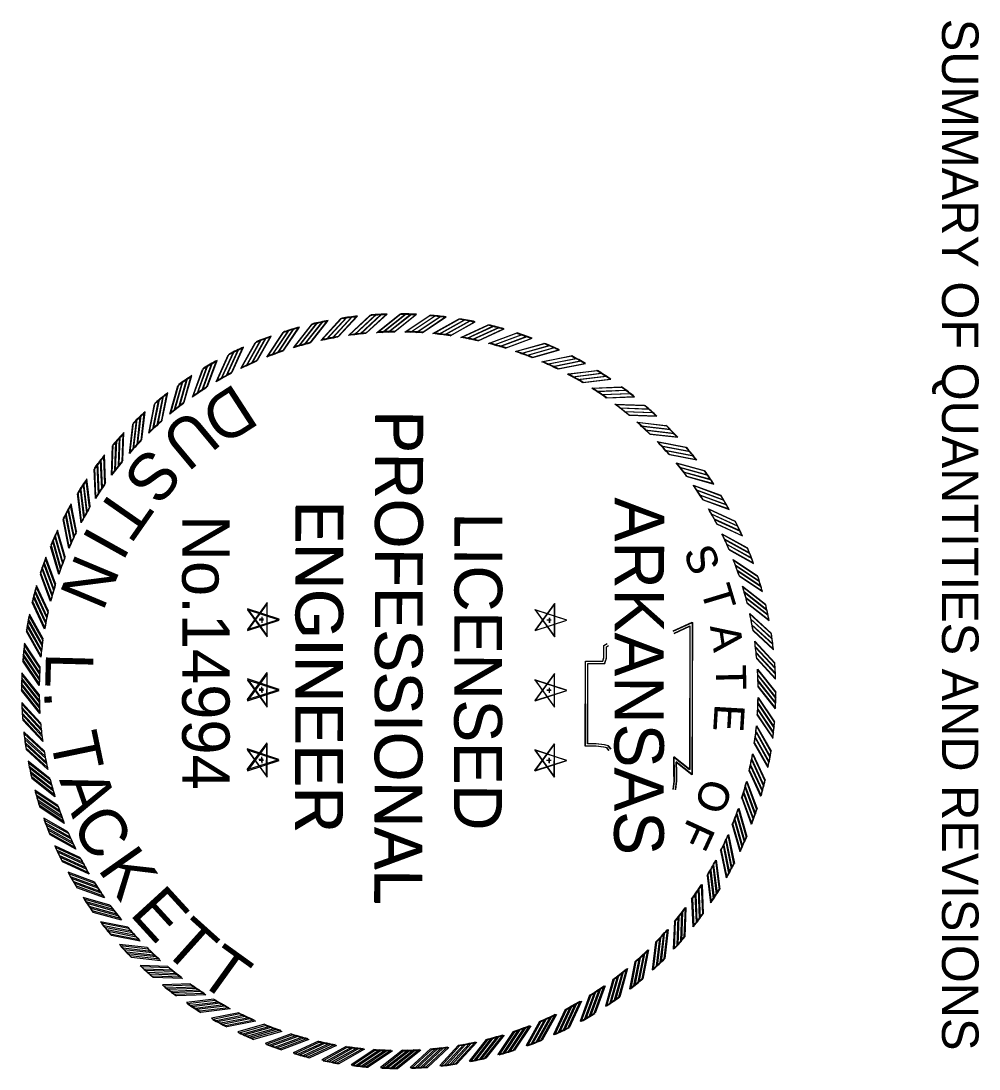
# Model space of a CAD drawing. Extents: x -206535075 to -206533174, y 123969740 to 123973355.
# Drawn here: x -206533482.2 to -206533174.1, y 123970261.6 to 123970598.7 of the extents above; entities that cross this region are included whole.
import ezdxf

# ---------------------------------------------------------------- set-up
doc = ezdxf.new("R2010")
doc.units = 0
doc.layers.add('54', color=7, linetype='Continuous')
doc.layers.add('Default', color=7, linetype='Continuous')

# ---------------------------------------------------------------- blocks, each defined once
blk = doc.blocks.new('STAR')
at = {"layer": 'Default'}
for p, q in [((-0.0001, 0.0615), (-0.0366, -0.0504)), ((0.0362, -0.0503), (0, 0.0617)), ((0.0587, 0.0188), (-0.059, 0.0189)), ((-0.0589, 0.0188), (0.0363, -0.0505)), ((-0.0365, -0.0503), (0.0589, 0.0188)), ((-0.0085, 0), (0.009, 0)), ((0, 0.0063), (0, -0.0085))]:
    blk.add_line(p, q, dxfattribs=at)
blk = doc.blocks.new('RP')
at = {"layer": 'Default'}
for p, q in [((-0.0781, 1.2656), (0.003, 1.33)), ((-0.058, 1.2667), (0.0216, 1.3299)), ((-0.0375, 1.2674), (0.0405, 1.3294)), ((-0.0176, 1.2679), (0.059, 1.3287))]:
    blk.add_line(p, q, dxfattribs=at)
for radius, start, end in [(1.33, 87.4562, 89.8699), (1.268, 90.7933, 93.5307)]:
    blk.add_arc((0, 0), radius, start, end, dxfattribs=at)

msp = doc.modelspace()

# ---------------------------------------------------------------- linework, layer by layer
at = {"layer": 'Default'}
for points in [[(-206533272.5, 123970402.48), (-206533266.36, 123970405.32), (-206533266.33, 123970356.28), (-206533271.48, 123970360.38), (-206533271.44, 123970357.04), (-206533271.4, 123970354.26), (-206533271.7, 123970351.48)], [(-206533272.47, 123970402.39), (-206533266.32, 123970405.2), (-206533266.46, 123970356.16), (-206533271.59, 123970360.28), (-206533271.56, 123970356.94), (-206533271.53, 123970354.16), (-206533271.85, 123970351.38)], [(-206533272.14, 123970401.68), (-206533267.1, 123970403.99), (-206533267.23, 123970357.77), (-206533272.38, 123970361.91), (-206533272.34, 123970356.94), (-206533272.31, 123970354.2), (-206533272.62, 123970351.47)], [(-206533272.17, 123970401.78), (-206533267.14, 123970404.11), (-206533267.11, 123970357.89), (-206533272.28, 123970362), (-206533272.21, 123970357.03), (-206533272.18, 123970354.3), (-206533272.48, 123970351.56)], [(-206533293.15, 123970363.98), (-206533293.83, 123970364.82), (-206533294.84, 123970365.1), (-206533297.38, 123970365.39), (-206533300.77, 123970365.4), (-206533300.68, 123970392.77), (-206533296.1, 123970392.76), (-206533295.09, 123970392.75), (-206533294.74, 123970393.86), (-206533294.73, 123970397.76), (-206533293.67, 123970398.45)], [(-206533293.05, 123970364.01), (-206533293.73, 123970364.84), (-206533294.75, 123970365.12), (-206533297.29, 123970365.4), (-206533300.68, 123970365.4), (-206533300.68, 123970392.77), (-206533296.1, 123970392.77), (-206533295.09, 123970392.77), (-206533294.75, 123970393.88), (-206533294.75, 123970397.78), (-206533293.69, 123970398.47)], [(-206533292.55, 123970364.47), (-206533293.38, 123970365.5), (-206533294.7, 123970365.86), (-206533297.34, 123970366.16), (-206533299.99, 123970366.17), (-206533299.91, 123970391.99), (-206533296.11, 123970391.98), (-206533294.52, 123970391.98), (-206533293.97, 123970393.74), (-206533293.96, 123970397.34), (-206533293.25, 123970397.79)], [(-206533292.45, 123970364.5), (-206533293.29, 123970365.53), (-206533294.6, 123970365.89), (-206533297.25, 123970366.17), (-206533299.9, 123970366.17), (-206533299.9, 123970392), (-206533296.1, 123970392), (-206533294.51, 123970392), (-206533293.97, 123970393.77), (-206533293.97, 123970397.36), (-206533293.27, 123970397.82)]]:
    msp.add_lwpolyline(points, dxfattribs=at)

# ---------------------------------------------------------------- block references
for name, p, xscale, yscale, rotation in [('RP', (-206533360.74, 123970383.01), 91.17655343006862, 91.17655343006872, 13.50000010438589), ('RP', (-206533360.78, 123970383.21), 91.1765534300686, 91.17655343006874, 13.304199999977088), ('RP', (-206533360.74, 123970383.01), 91.1765534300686, 91.1765534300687, 9.00000010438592), ('RP', (-206533360.78, 123970383.21), 91.17655343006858, 91.17655343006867, 8.80419999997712), ('RP', (-206533360.74, 123970383.01), 91.17655343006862, 91.17655343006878, 4.500000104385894), ('RP', (-206533360.78, 123970383.21), 91.17655343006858, 91.17655343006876, 4.304199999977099), ('RP', (-206533360.74, 123970383.01), 91.17655343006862, 91.17655343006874, 1.0438590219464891e-07), ('RP', (-206533360.78, 123970383.21), 91.1765534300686, 91.17655343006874, -0.19580000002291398), ('RP', (-206533360.74, 123970383.01), 91.1765534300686, 91.17655343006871, -4.499999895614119), ('RP', (-206533360.78, 123970383.21), 91.17655343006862, 91.17655343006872, -4.695800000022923), ('RP', (-206533360.74, 123970383.01), 91.17655343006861, 91.17655343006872, -8.999999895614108), ('RP', (-206533360.78, 123970383.21), 91.17655343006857, 91.17655343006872, -9.195800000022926), ('RP', (-206533360.74, 123970383.01), 91.17655343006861, 91.17655343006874, -13.49999989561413), ('RP', (-206533360.78, 123970383.21), 91.1765534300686, 91.17655343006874, -13.69580000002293), ('RP', (-206533360.74, 123970383.01), 91.17655343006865, 91.17655343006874, 18.000000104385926), ('RP', (-206533360.78, 123970383.21), 91.1765534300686, 91.17655343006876, 17.804199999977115), ('RP', (-206533360.74, 123970383.01), 91.17655343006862, 91.17655343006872, -17.99999989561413), ('RP', (-206533360.78, 123970383.21), 91.17655343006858, 91.17655343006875, -18.195800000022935), ('RP', (-206533360.74, 123970383.01), 91.17655343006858, 91.17655343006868, 22.500000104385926), ('RP', (-206533360.78, 123970383.21), 91.17655343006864, 91.17655343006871, 22.30419999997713), ('RP', (-206533360.74, 123970383.01), 91.17655343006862, 91.17655343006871, -22.49999989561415), ('RP', (-206533360.78, 123970383.21), 91.1765534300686, 91.1765534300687, -22.69580000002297), ('RP', (-206533360.74, 123970383.01), 91.17655343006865, 91.17655343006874, 27.000000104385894), ('RP', (-206533360.78, 123970383.21), 91.17655343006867, 91.17655343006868, 26.804199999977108), ('RP', (-206533360.74, 123970383.01), 91.17655343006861, 91.1765534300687, -26.999999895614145), ('RP', (-206533360.78, 123970383.21), 91.17655343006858, 91.17655343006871, -27.195800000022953), ('RP', (-206533360.74, 123970383.01), 91.17655343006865, 91.17655343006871, 31.500000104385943), ('RP', (-206533360.78, 123970383.21), 91.17655343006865, 91.17655343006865, 31.304199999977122), ('RP', (-206533360.74, 123970383.01), 91.1765534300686, 91.1765534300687, -31.49999989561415), ('RP', (-206533360.78, 123970383.21), 91.17655343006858, 91.17655343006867, -31.69580000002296), ('RP', (-206533360.74, 123970383.01), 91.17655343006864, 91.1765534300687, -35.99999989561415), ('RP', (-206533360.78, 123970383.21), 91.17655343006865, 91.17655343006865, -36.19580000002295), ('RP', (-206533360.74, 123970383.01), 91.17655343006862, 91.17655343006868, 36.00000010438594), ('RP', (-206533360.78, 123970383.21), 91.17655343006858, 91.17655343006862, 35.80419999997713), ('RP', (-206533360.74, 123970383.01), 91.17655343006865, 91.17655343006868, 40.500000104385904), ('RP', (-206533360.78, 123970383.21), 91.17655343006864, 91.17655343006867, 40.30419999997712), ('RP', (-206533360.74, 123970383.01), 91.17655343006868, 91.17655343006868, -40.49999989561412), ('RP', (-206533360.78, 123970383.21), 91.17655343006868, 91.17655343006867, -40.695800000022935), ('RP', (-206533360.74, 123970383.01), 91.17655343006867, 91.17655343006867, 45.00000010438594), ('RP', (-206533360.78, 123970383.21), 91.17655343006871, 91.17655343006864, 44.80419999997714), ('RP', (-206533360.74, 123970383.01), 91.17655343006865, 91.17655343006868, -44.999999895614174), ('RP', (-206533360.78, 123970383.21), 91.17655343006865, 91.1765534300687, -45.19580000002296), ('RP', (-206533360.74, 123970383.01), 91.17655343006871, 91.1765534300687, 49.50000010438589), ('RP', (-206533360.78, 123970383.21), 91.17655343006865, 91.17655343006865, 49.304199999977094), ('RP', (-206533360.74, 123970383.01), 91.17655343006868, 91.17655343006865, -49.499999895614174), ('RP', (-206533360.78, 123970383.21), 91.17655343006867, 91.17655343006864, -49.69580000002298), ('RP', (-206533360.74, 123970383.01), 91.17655343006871, 91.17655343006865, 54.00000010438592), ('RP', (-206533360.78, 123970383.21), 91.17655343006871, 91.17655343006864, 53.80419999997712), ('RP', (-206533360.74, 123970383.01), 91.17655343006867, 91.17655343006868, -53.999999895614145), ('RP', (-206533360.78, 123970383.21), 91.17655343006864, 91.17655343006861, -54.195800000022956), ('RP', (-206533360.78, 123970383.21), 91.17655343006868, 91.17655343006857, 58.304199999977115), ('RP', (-206533360.74, 123970383.01), 91.17655343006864, 91.17655343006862, -58.49999989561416), ('RP', (-206533360.78, 123970383.21), 91.17655343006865, 91.1765534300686, -58.695800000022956), ('RP', (-206533360.74, 123970383.01), 91.1765534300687, 91.1765534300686, 58.50000010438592), ('RP', (-206533360.74, 123970383.01), 91.17655343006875, 91.17655343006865, 63.00000010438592), ('RP', (-206533360.78, 123970383.21), 91.17655343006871, 91.17655343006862, 62.8041999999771), ('RP', (-206533360.74, 123970383.01), 91.17655343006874, 91.17655343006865, -62.99999989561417), ('RP', (-206533360.78, 123970383.21), 91.17655343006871, 91.17655343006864, -63.19580000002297), ('RP', (-206533360.78, 123970383.21), 91.17655343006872, 91.17655343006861, 67.30419999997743), ('RP', (-206533360.74, 123970383.01), 91.1765534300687, 91.17655343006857, -67.49999989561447), ('RP', (-206533360.78, 123970383.21), 91.17655343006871, 91.17655343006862, -67.6958000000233), ('RP', (-206533360.74, 123970383.01), 91.17655343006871, 91.17655343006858, 67.50000010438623), ('RP', (-206533360.74, 123970383.01), 91.17655343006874, 91.17655343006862, 72.0000001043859), ('RP', (-206533360.78, 123970383.21), 91.17655343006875, 91.1765534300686, 71.80419999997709), ('RP', (-206533360.74, 123970383.01), 91.17655343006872, 91.17655343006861, -71.99999989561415), ('RP', (-206533360.78, 123970383.21), 91.17655343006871, 91.1765534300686, -72.19580000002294), ('RP', (-206533360.74, 123970383.01), 91.17655343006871, 91.1765534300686, -76.49999989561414), ('RP', (-206533360.78, 123970383.21), 91.17655343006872, 91.17655343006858, -76.69580000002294), ('RP', (-206533360.74, 123970383.01), 91.17655343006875, 91.1765534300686, 76.50000010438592), ('RP', (-206533360.78, 123970383.21), 91.17655343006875, 91.17655343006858, 76.3041999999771), ('STAR', (-206533404.81, 123970405.9), 91.17655343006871, 91.17655343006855, -89.99999989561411), ('STAR', (-206533404.76, 123970406.26), 91.17655343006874, 91.1765534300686, -90.19580000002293), ('STAR', (-206533312.33, 123970405.9), 91.17655343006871, 91.17655343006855, -89.99999989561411), ('STAR', (-206533312.28, 123970405.94), 91.17655343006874, 91.1765534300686, -90.19580000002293), ('RP', (-206533360.78, 123970383.21), 91.17655343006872, 91.17655343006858, 80.8041999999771), ('RP', (-206533360.74, 123970383.01), 91.17655343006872, 91.17655343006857, -80.99999989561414), ('RP', (-206533360.78, 123970383.21), 91.17655343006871, 91.17655343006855, -81.19580000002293), ('RP', (-206533360.74, 123970383.01), 91.17655343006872, 91.17655343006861, 81.0000001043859), ('RP', (-206533360.78, 123970383.21), 91.17655343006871, 91.17655343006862, 85.30419999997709), ('RP', (-206533360.74, 123970383.01), 91.17655343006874, 91.17655343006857, 85.5000001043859), ('RP', (-206533360.74, 123970383.01), 91.17655343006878, 91.17655343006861, -85.49999989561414), ('RP', (-206533360.78, 123970383.21), 91.17655343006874, 91.1765534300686, -85.69580000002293), ('RP', (-206533360.78, 123970383.21), 91.17655343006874, 91.1765534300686, 89.80419999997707), ('RP', (-206533360.74, 123970383.01), 91.17655343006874, 91.17655343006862, 90.00000010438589), ('STAR', (-206533404.84, 123970383.7), 91.17655343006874, 91.1765534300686, -90.19580000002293), ('STAR', (-206533404.81, 123970383.34), 91.17655343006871, 91.17655343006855, -89.99999989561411), ('STAR', (-206533312.36, 123970383.38), 91.17655343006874, 91.1765534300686, -90.19580000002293), ('STAR', (-206533312.33, 123970383.34), 91.17655343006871, 91.17655343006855, -89.99999989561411), ('RP', (-206533360.78, 123970383.21), 91.17655343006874, 91.1765534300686, -90.19580000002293), ('RP', (-206533360.74, 123970383.01), 91.17655343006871, 91.17655343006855, -89.99999989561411), ('RP', (-206533360.78, 123970383.21), 91.17655343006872, 91.17655343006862, -94.69580000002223), ('RP', (-206533360.74, 123970383.01), 91.17655343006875, 91.17655343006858, -94.49999989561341), ('RP', (-206533360.78, 123970383.21), 91.1765534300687, 91.17655343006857, 94.30419999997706), ('RP', (-206533360.74, 123970383.01), 91.17655343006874, 91.17655343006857, 94.50000010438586), ('RP', (-206533360.78, 123970383.21), 91.17655343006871, 91.1765534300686, 98.80419999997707), ('RP', (-206533360.78, 123970383.21), 91.17655343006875, 91.17655343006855, -99.19580000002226), ('RP', (-206533360.74, 123970383.01), 91.17655343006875, 91.1765534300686, -98.99999989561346), ('RP', (-206533360.74, 123970383.01), 91.17655343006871, 91.17655343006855, 99.00000010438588), ('STAR', (-206533404.92, 123970361.15), 91.17655343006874, 91.1765534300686, -90.19580000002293), ('STAR', (-206533404.81, 123970360.79), 91.17655343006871, 91.17655343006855, -89.99999989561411), ('STAR', (-206533312.44, 123970360.83), 91.17655343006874, 91.1765534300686, -90.19580000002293), ('STAR', (-206533312.33, 123970360.79), 91.17655343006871, 91.17655343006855, -89.99999989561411), ('RP', (-206533360.78, 123970383.21), 91.1765534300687, 91.1765534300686, 103.30419999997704), ('RP', (-206533360.74, 123970383.01), 91.17655343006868, 91.17655343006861, 103.50000010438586), ('RP', (-206533360.78, 123970383.21), 91.17655343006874, 91.17655343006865, -103.69580000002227), ('RP', (-206533360.74, 123970383.01), 91.17655343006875, 91.17655343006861, -103.49999989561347), ('RP', (-206533360.78, 123970383.21), 91.17655343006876, 91.1765534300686, -108.19580000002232), ('RP', (-206533360.74, 123970383.01), 91.17655343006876, 91.17655343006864, -107.99999989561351), ('RP', (-206533360.78, 123970383.21), 91.17655343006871, 91.17655343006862, 107.80419999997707), ('RP', (-206533360.74, 123970383.01), 91.17655343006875, 91.17655343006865, 108.00000010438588), ('RP', (-206533360.78, 123970383.21), 91.17655343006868, 91.17655343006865, 112.3041999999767), ('RP', (-206533360.74, 123970383.01), 91.17655343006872, 91.17655343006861, 112.50000010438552), ('RP', (-206533360.78, 123970383.21), 91.17655343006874, 91.1765534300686, -112.69580000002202), ('RP', (-206533360.74, 123970383.01), 91.17655343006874, 91.1765534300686, -112.49999989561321), ('RP', (-206533360.78, 123970383.21), 91.1765534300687, 91.17655343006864, -117.19580000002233), ('RP', (-206533360.74, 123970383.01), 91.1765534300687, 91.1765534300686, -116.99999989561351), ('RP', (-206533360.78, 123970383.21), 91.17655343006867, 91.17655343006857, 116.80419999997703), ('RP', (-206533360.74, 123970383.01), 91.17655343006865, 91.1765534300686, 117.00000010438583), ('RP', (-206533360.78, 123970383.21), 91.17655343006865, 91.1765534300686, 121.30419999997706), ('RP', (-206533360.74, 123970383.01), 91.17655343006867, 91.17655343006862, 121.50000010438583), ('RP', (-206533360.78, 123970383.21), 91.17655343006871, 91.17655343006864, -121.69580000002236), ('RP', (-206533360.74, 123970383.01), 91.17655343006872, 91.17655343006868, -121.49999989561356), ('RP', (-206533360.78, 123970383.21), 91.17655343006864, 91.17655343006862, 125.804199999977), ('RP', (-206533360.78, 123970383.21), 91.1765534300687, 91.1765534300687, -126.19580000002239), ('RP', (-206533360.74, 123970383.01), 91.17655343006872, 91.17655343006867, -125.99999989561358), ('RP', (-206533360.74, 123970383.01), 91.17655343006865, 91.17655343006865, 126.00000010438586), ('RP', (-206533360.78, 123970383.21), 91.17655343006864, 91.17655343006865, -130.69580000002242), ('RP', (-206533360.74, 123970383.01), 91.17655343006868, 91.17655343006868, -130.4999998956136), ('RP', (-206533360.78, 123970383.21), 91.17655343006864, 91.17655343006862, 130.30419999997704), ('RP', (-206533360.74, 123970383.01), 91.17655343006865, 91.1765534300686, 130.50000010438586), ('RP', (-206533360.78, 123970383.21), 91.17655343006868, 91.17655343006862, -135.19580000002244), ('RP', (-206533360.74, 123970383.01), 91.17655343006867, 91.17655343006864, -134.9999998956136), ('RP', (-206533360.78, 123970383.21), 91.17655343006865, 91.1765534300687, 134.80419999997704), ('RP', (-206533360.74, 123970383.01), 91.17655343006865, 91.17655343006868, 135.00000010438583), ('RP', (-206533360.78, 123970383.21), 91.17655343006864, 91.17655343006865, -139.69580000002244), ('RP', (-206533360.74, 123970383.01), 91.17655343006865, 91.17655343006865, -139.49999989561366), ('RP', (-206533360.78, 123970383.21), 91.17655343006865, 91.17655343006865, 139.30419999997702), ('RP', (-206533360.74, 123970383.01), 91.1765534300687, 91.17655343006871, 139.50000010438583), ('RP', (-206533360.78, 123970383.21), 91.17655343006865, 91.1765534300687, 143.80419999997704), ('RP', (-206533360.78, 123970383.21), 91.17655343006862, 91.17655343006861, -144.19580000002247), ('RP', (-206533360.74, 123970383.01), 91.1765534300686, 91.17655343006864, -143.99999989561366), ('RP', (-206533360.74, 123970383.01), 91.17655343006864, 91.17655343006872, 144.00000010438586), ('RP', (-206533360.78, 123970383.21), 91.1765534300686, 91.17655343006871, 148.30419999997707), ('RP', (-206533360.74, 123970383.01), 91.17655343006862, 91.17655343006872, 148.5000001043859), ('RP', (-206533360.78, 123970383.21), 91.17655343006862, 91.17655343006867, -148.6958000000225), ('RP', (-206533360.74, 123970383.01), 91.17655343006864, 91.17655343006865, -148.4999998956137), ('RP', (-206533360.78, 123970383.21), 91.17655343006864, 91.17655343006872, 152.80419999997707), ('RP', (-206533360.78, 123970383.21), 91.17655343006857, 91.17655343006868, -153.19580000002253), ('RP', (-206533360.74, 123970383.01), 91.17655343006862, 91.17655343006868, -152.99999989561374), ('RP', (-206533360.74, 123970383.01), 91.17655343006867, 91.17655343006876, 153.00000010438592), ('RP', (-206533360.78, 123970383.21), 91.17655343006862, 91.17655343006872, 157.30419999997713), ('RP', (-206533360.74, 123970383.01), 91.17655343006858, 91.17655343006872, 157.50000010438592), ('RP', (-206533360.78, 123970383.21), 91.17655343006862, 91.17655343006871, -157.69580000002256), ('RP', (-206533360.74, 123970383.01), 91.17655343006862, 91.17655343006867, -157.49999989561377), ('RP', (-206533360.78, 123970383.21), 91.17655343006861, 91.17655343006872, 161.8041999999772), ('RP', (-206533360.74, 123970383.01), 91.1765534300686, 91.1765534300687, 162.00000010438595), ('RP', (-206533360.78, 123970383.21), 91.1765534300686, 91.1765534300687, -162.1958000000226), ('RP', (-206533360.74, 123970383.01), 91.17655343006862, 91.17655343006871, -161.9999998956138), ('RP', (-206533360.78, 123970383.21), 91.1765534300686, 91.1765534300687, 166.3041999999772), ('RP', (-206533360.74, 123970383.01), 91.1765534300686, 91.17655343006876, 166.500000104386), ('RP', (-206533360.78, 123970383.21), 91.17655343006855, 91.17655343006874, 170.80419999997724), ('RP', (-206533360.74, 123970383.01), 91.1765534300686, 91.17655343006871, 171.00000010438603), ('RP', (-206533360.78, 123970383.21), 91.1765534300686, 91.1765534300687, -171.19580000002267), ('RP', (-206533360.74, 123970383.01), 91.17655343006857, 91.17655343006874, -170.99999989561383), ('RP', (-206533360.78, 123970383.21), 91.17655343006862, 91.17655343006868, -166.69580000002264), ('RP', (-206533360.74, 123970383.01), 91.17655343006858, 91.17655343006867, -166.49999989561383), ('RP', (-206533360.78, 123970383.21), 91.1765534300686, 91.17655343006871, 175.30419999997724), ('RP', (-206533360.74, 123970383.01), 91.17655343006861, 91.17655343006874, 175.50000010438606), ('RP', (-206533360.78, 123970383.21), 91.1765534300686, 91.17655343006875, 179.80419999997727), ('RP', (-206533360.74, 123970383.01), 91.17655343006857, 91.17655343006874, -179.9999998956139), ('RP', (-206533360.78, 123970383.21), 91.17655343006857, 91.17655343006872, -175.6958000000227), ('RP', (-206533360.74, 123970383.01), 91.17655343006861, 91.17655343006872, -175.49999989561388)]:
    msp.add_blockref(name, p, dxfattribs=dict(at, xscale=xscale, yscale=yscale, rotation=rotation))

# ---------------------------------------------------------------- texts
at = {"layer": '54'}
msp.add_text('SUMMARY OF QUANTITIES AND REVISIONS', height=11.724, rotation=270, dxfattribs=at).set_placement((-206533186.03, 123970599.39))
at = {"layer": 'Default'}
for s, height, rotation, p in [('D', 15.28, 212.9045, (-206533413.3, 123970482.36)), ('U', 15.28, 219.8131, (-206533426.92, 123970474.61)), ('PROFESSIONAL', 15.2848, 269.8042, (-206533368.11, 123970473.49)), ('PROFESSIONAL', 15.2848, 270, (-206533368.39, 123970473.26)), ('S', 15.28, 230.368, (-206533441.21, 123970462.3)), ('T', 15.28, 235.101, (-206533451.64, 123970449.96)), ('ARKANSAS', 15.788, 269.8042, (-206533291.11, 123970445.38)), ('ARKANSAS', 15.788, 270, (-206533291.29, 123970445.41)), ('ENGINEER', 15.285, 270, (-206533393.95, 123970444.15)), ('ENGINEER', 15.285, 269.8042, (-206533393.77, 123970444.46)), ('No.14994', 15.225, 270, (-206533430.38, 123970439.68)), ('LICENSED', 15.285, 269.8042, (-206533342.66, 123970440.65)), ('LICENSED', 15.285, 270, (-206533342.82, 123970440.51)), ('I', 15.28, 240.8687, (-206533460.18, 123970436.82)), ('S', 9.67, 289.7726, (-206533269.28, 123970428.03)), ('S', 9.67, 289.5768, (-206533269.16, 123970427.92)), ('N', 15.28, 247.2539, (-206533464.32, 123970427.96)), ('T', 9.67, 286.9015, (-206533263.76, 123970415.73)), ('T', 9.67, 286.7057, (-206533263.68, 123970415.6)), ('A', 9.67, 278.6788, (-206533260.69, 123970403.98)), ('A', 9.67, 278.483, (-206533260.66, 123970403.84)), ('L', 15.28, 268.474, (-206533474.16, 123970395.62)), ('T', 9.67, 271.2831, (-206533258.77, 123970391.34)), ('T', 9.67, 271.4789, (-206533258.77, 123970391.49)), ('.', 15.28, 274.1489, (-206533474.9, 123970383.13)), ('E', 9.67, 266.4762, (-206533259.11, 123970378.96)), ('E', 9.67, 266.672, (-206533259.06, 123970379.11)), ('T', 15.28, 281.7303, (-206533472.98, 123970368.25)), ('A', 15.28, 289.3817, (-206533470, 123970354.6)), ('O', 9.67, 251.026, (-206533262.51, 123970355.49)), ('O', 9.67, 251.2218, (-206533262.38, 123970355.62)), ('C', 15.28, 303.6577, (-206533466.49, 123970339.92)), ('F', 9.67, 245.167, (-206533267.65, 123970342.47)), ('F', 9.67, 245.3628, (-206533267.48, 123970342.58)), ('K', 15.28, 305.1218, (-206533457.79, 123970325.88)), ('E', 15.28, 312.4392, (-206533447.57, 123970311.35)), ('T', 15.28, 318.0746, (-206533437.28, 123970299.89)), ('T', 15.28, 324.3036, (-206533425.95, 123970289.93))]:
    msp.add_text(s, height=height, rotation=rotation, dxfattribs=at).set_placement(p)

doc.saveas('drawing.dxf')
